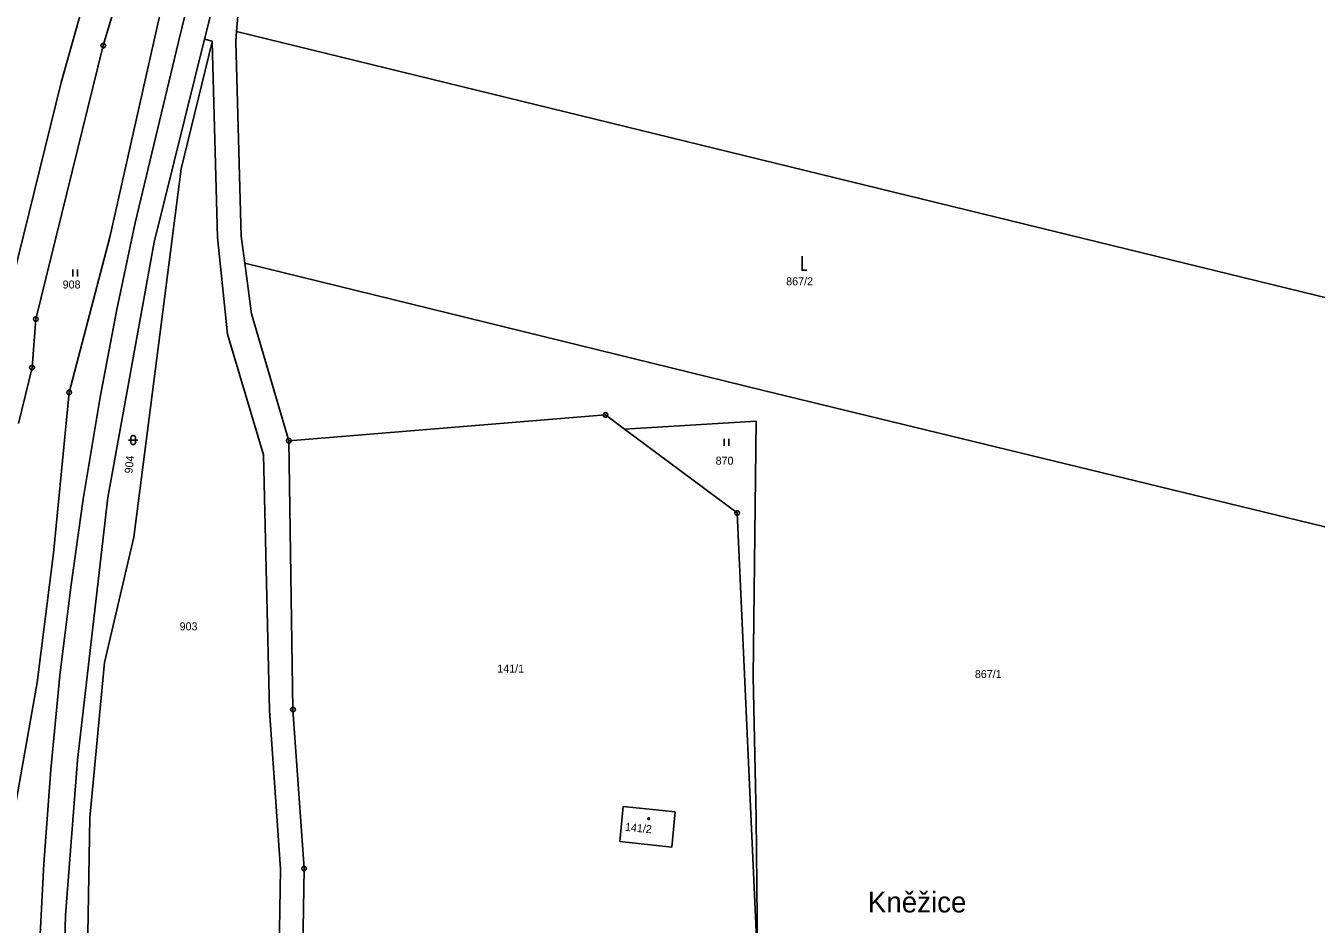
# Model space of a CAD drawing. Extents: x -812394 to -807601, y -1013098 to -1009266.
# Drawn here: x -809886.4 to -809612.2, y -1010592.7 to -1010401.8 of the extents above; entities that cross this region are included whole.
import ezdxf

# ---------------------------------------------------------------- set-up
doc = ezdxf.new("R2010")
doc.units = 0
for name, color, linetype in [('KN_HRANICE', 7, 'Continuous'), ('KN_KULTURY', 7, 'Continuous'), ('KN_MEZNIKY', 7, 'Continuous'), ('KN_PARCELY', 7, 'Continuous'), ('KN_VEDENI', 7, 'Continuous')]:
    doc.layers.add(name, color=color, linetype=linetype)

# ---------------------------------------------------------------- blocks, each defined once
blk = doc.blocks.new('302')
blk.add_lwpolyline([(0, 3), (0, 0), (1, 0)])
blk = doc.blocks.new('306')
for p, q in [((-0.5, 1.5), (-0.5, 0)), ((0.5, 0), (0.5, 1.5))]:
    blk.add_line(p, q)
blk = doc.blocks.new('316')
for points in [[(-1, 1), (0.27, 1), (1, 1)], [(-0.5, 1.5), (-0.4, 1.79), (-0.15, 1.97), (0.16, 1.97), (0.41, 1.79), (0.51, 1.5), (0.51, 0.5), (0.41, 0.21), (0.16, 0.03), (-0.15, 0.03), (-0.4, 0.21), (-0.5, 0.5), (-0.5, 1.5)]]:
    blk.add_lwpolyline(points)
blk = doc.blocks.new('105')
blk.add_line((-0.12, 0), (0.12, 0))
blk.add_lwpolyline([(0.15, 0.48), (0.4, 0.3), (0.5, 0.01), (0.4, -0.28), (0.15, -0.46), (-0.16, -0.46), (-0.41, -0.28), (-0.51, 0.01), (-0.41, 0.3), (-0.16, 0.48), (0.15, 0.48)])
blk = doc.blocks.new('402')
blk.add_lwpolyline([(0.09, 0.15), (0.18, 0), (0.09, -0.15), (-0.09, -0.15), (-0.18, 0), (-0.09, 0.15), (0.09, 0.15)])

msp = doc.modelspace()

# ---------------------------------------------------------------- linework, layer by layer
at = {"layer": 'KN_HRANICE'}
for p, q in [((-809864.27, -1010361.43), (-809878.82, -1010413.89)), ((-809869.89, -1010406.06), (-809858.75, -1010368.45)), ((-809842.4, -1010380.57), (-809848.37, -1010404.67)), ((-809841.57, -1010403.09), (-809840.96, -1010395.38)), ((-809841.74, -1010405.27), (-809841.57, -1010403.09)), ((-809714.42, -1010434.16), (-809841.57, -1010403.09)), ((-809884.23, -1010464.16), (-809869.89, -1010406.06)), ((-809848.37, -1010404.67), (-809859.05, -1010447.8)), ((-809853.38, -1010432.24), (-809846.74, -1010405.27)), ((-809848.37, -1010404.67), (-809846.74, -1010405.14)), ((-809846.74, -1010405.14), (-809846.74, -1010405.27)), ((-809846.74, -1010405.27), (-809845.6, -1010446.84)), ((-809840.6, -1010446.52), (-809841.74, -1010405.27)), ((-809878.82, -1010413.89), (-809894.45, -1010477.13)), ((-809863.41, -1010510.51), (-809853.38, -1010432.24)), ((-809587.27, -1010465.23), (-809714.42, -1010434.16)), ((-809845.6, -1010446.84), (-809843.49, -1010467.38)), ((-809840.6, -1010446.52), (-809839.82, -1010452.31)), ((-809859.05, -1010447.8), (-809868.93, -1010502.05)), ((-809839.82, -1010452.31), (-809838.38, -1010463.06)), ((-809839.82, -1010452.31), (-809729.65, -1010479.3)), ((-809830.46, -1010490), (-809838.38, -1010463.06)), ((-809885.03, -1010474.47), (-809884.23, -1010464.16)), ((-809843.49, -1010467.38), (-809835.86, -1010493.01)), ((-809887.91, -1010486.35), (-809885.03, -1010474.47)), ((-809729.65, -1010479.3), (-809588.81, -1010513.56)), ((-809763.21, -1010484.53), (-809830.46, -1010490)), ((-809759.15, -1010487.55), (-809763.21, -1010484.53)), ((-809731.23, -1010485.87), (-809759.15, -1010487.55)), ((-809735.22, -1010505.35), (-809759.15, -1010487.55)), ((-809731.8, -1010540.09), (-809731.23, -1010485.87)), ((-809830.46, -1010490), (-809829.59, -1010547.11)), ((-809835.86, -1010493.01), (-809834.59, -1010547.32)), ((-809868.93, -1010502.05), (-809875.4, -1010557.89)), ((-809730.9, -1010600.87), (-809735.22, -1010505.35)), ((-809869.64, -1010537.09), (-809863.41, -1010510.51)), ((-809872.78, -1010570.15), (-809869.64, -1010537.09)), ((-809731.22, -1010570.09), (-809731.8, -1010540.09)), ((-809834.59, -1010547.32), (-809832.23, -1010581.05)), ((-809829.59, -1010547.11), (-809827.23, -1010580.92)), ((-809875.4, -1010557.89), (-809877.92, -1010590.8)), ((-809760.19, -1010575.15), (-809759.48, -1010567.72)), ((-809759.48, -1010567.72), (-809748.44, -1010568.84)), ((-809873.36, -1010604.47), (-809872.78, -1010570.15)), ((-809748.44, -1010568.84), (-809749.12, -1010576.39)), ((-809730.9, -1010600.87), (-809731.22, -1010570.09)), ((-809749.12, -1010576.39), (-809760.19, -1010575.15)), ((-809832.23, -1010581.05), (-809832.51, -1010598.19)), ((-809827.23, -1010580.92), (-809827.51, -1010598.06)), ((-809877.92, -1010590.8), (-809879.03, -1010627.62))]:
    msp.add_line(p, q, dxfattribs=at)
msp.add_lwpolyline([(-809898.33, -1010631.14), (-809892.3, -1010585.73), (-809889.06, -1010570.22), (-809883.97, -1010541.36), (-809880.44, -1010513.89), (-809877.14, -1010479.74), (-809868.51, -1010446.75), (-809850.96, -1010368.61), (-809838.06, -1010317.02)], dxfattribs=at)
at = {"layer": 'KN_VEDENI'}
for p, q in [((-809853.91, -1010405.23), (-809839.54, -1010346.64)), ((-809859.14, -1010427.1), (-809853.91, -1010405.23)), ((-809863.14, -1010443.73), (-809859.14, -1010427.1)), ((-809867.03, -1010462.14), (-809863.14, -1010443.73)), ((-809870.53, -1010480.75), (-809867.03, -1010462.14)), ((-809874.15, -1010502.44), (-809870.53, -1010480.75)), ((-809876.79, -1010521.14), (-809874.15, -1010502.44)), ((-809879.09, -1010539.87), (-809876.79, -1010521.14)), ((-809881, -1010559.84), (-809879.09, -1010539.87)), ((-809882.5, -1010579.93), (-809881, -1010559.84)), ((-809883.6, -1010600.07), (-809882.5, -1010579.93))]:
    msp.add_line(p, q, dxfattribs=at)

# ---------------------------------------------------------------- block references
at = {"layer": 'KN_KULTURY'}
for name, p in [('302', (-809721.44, -1010453.78)), ('306', (-809875.85, -1010455.12)), ('316', (-809863.55, -1010490.87)), ('306', (-809737.47, -1010491.07)), ('402', (-809754.04, -1010570.3))]:
    msp.add_blockref(name, p, dxfattribs=at)
at = {"layer": 'KN_MEZNIKY'}
for p in [(-809869.89, -1010406.06), (-809884.23, -1010464.16), (-809885.03, -1010474.47), (-809877.14, -1010479.74), (-809763.21, -1010484.53), (-809830.46, -1010490), (-809735.22, -1010505.35), (-809829.59, -1010547.11), (-809827.23, -1010580.92)]:
    msp.add_blockref('105', p, dxfattribs=at)

# ---------------------------------------------------------------- texts
at = {"layer": 'KN_PARCELY'}
for s, height, p in [('867/2', 1.7, (-809724.82, -1010456.99)), ('908', 1.7, (-809878.52, -1010457.66)), ('870', 1.7, (-809739.81, -1010495.1)), ('903', 1.7, (-809853.67, -1010530.29)), ('141/1', 1.7, (-809786.18, -1010539.25)), ('867/1', 1.7, (-809684.74, -1010540.42)), ('Kněžice', 4.4, (-809707.47, -1010590.23))]:
    msp.add_text(s, height=height, dxfattribs=at).set_placement(p)
for s, rotation, p in [('904', 84.74, (-809863.69, -1010497.03)), ('141/2', 354.374, (-809759.12, -1010572.87))]:
    msp.add_text(s, height=1.7, rotation=rotation, dxfattribs=at).set_placement(p)

doc.saveas('drawing.dxf')
